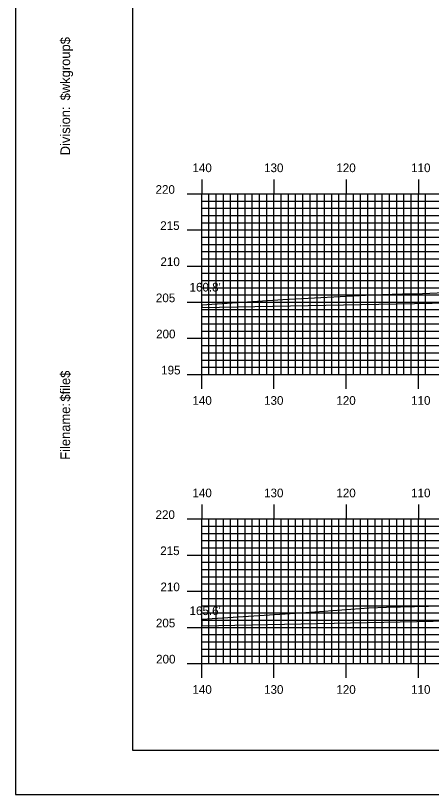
# Model space of a CAD drawing. Extents: x 1821605 to 1821948, y 442591 to 442811.
# Drawn here: x 1821605 to 1821662.5, y 442590.5 to 442698.3 of the extents above; entities that cross this region are included whole.
import ezdxf

# ---------------------------------------------------------------- set-up
doc = ezdxf.new("R2010")
doc.units = 0
for name, color, linetype in [('ANNOTATION', 7, 'Continuous'), ('BORDER', 7, 'Continuous'), ('D_Text_Standard', 7, 'Continuous'), ('H_V ANNOTATION', 7, 'Continuous'), ('MAJOR', 7, 'Continuous'), ('MINOR', 7, 'Continuous'), ('PLOT BOUNDARY', 7, 'Continuous'), ('S_Roadway_Centerline', 7, 'Continuous')]:
    doc.layers.add(name, color=color, linetype=linetype)

msp = doc.modelspace()

# ---------------------------------------------------------------- linework, layer by layer
at = {"layer": 'ANNOTATION'}
for p, q in [((1821726.4, 442659.78), (1821630.74, 442657.87)), ((1821630.74, 442658.31), (1821630.74, 442657.87)), ((1821726.4, 442615.77), (1821630.74, 442613.85)), ((1821630.74, 442614.78), (1821630.74, 442613.85))]:
    msp.add_line(p, q, dxfattribs=at)
at = {"layer": 'BORDER'}
msp.add_lwpolyline([(1821621.14, 442596.67), (1821941.14, 442596.67), (1821941.14, 442806.67), (1821621.14, 442806.67)], close=True, dxfattribs=at)
at = {"layer": 'MAJOR'}
for p, q in [((1821630.74, 442675.67), (1821630.74, 442673.67)), ((1821640.74, 442675.67), (1821640.74, 442673.67)), ((1821650.74, 442675.67), (1821650.74, 442673.67)), ((1821660.74, 442675.67), (1821660.74, 442673.67)), ((1821628.74, 442673.67), (1821630.74, 442673.67)), ((1821630.74, 442673.67), (1821910.74, 442673.67)), ((1821630.74, 442648.67), (1821630.74, 442673.67)), ((1821630.74, 442648.67), (1821630.74, 442673.67)), ((1821630.74, 442673.67), (1821910.74, 442673.67)), ((1821640.74, 442648.67), (1821640.74, 442673.67)), ((1821650.74, 442648.67), (1821650.74, 442673.67)), ((1821660.74, 442648.67), (1821660.74, 442673.67)), ((1821628.74, 442668.67), (1821630.74, 442668.67)), ((1821630.74, 442668.67), (1821910.74, 442668.67)), ((1821628.74, 442663.67), (1821630.74, 442663.67)), ((1821630.74, 442663.67), (1821910.74, 442663.67)), ((1821628.74, 442658.67), (1821630.74, 442658.67)), ((1821630.74, 442658.67), (1821910.74, 442658.67)), ((1821628.74, 442653.67), (1821630.74, 442653.67)), ((1821630.74, 442653.67), (1821910.74, 442653.67)), ((1821628.74, 442648.67), (1821630.74, 442648.67)), ((1821630.74, 442648.67), (1821910.74, 442648.67)), ((1821630.74, 442648.67), (1821910.74, 442648.67)), ((1821630.74, 442646.66), (1821630.74, 442648.67)), ((1821640.74, 442646.66), (1821640.74, 442648.67)), ((1821650.74, 442646.66), (1821650.74, 442648.67)), ((1821660.74, 442646.66), (1821660.74, 442648.67)), ((1821630.74, 442630.67), (1821630.74, 442628.67)), ((1821640.74, 442630.67), (1821640.74, 442628.67)), ((1821650.74, 442630.67), (1821650.74, 442628.67)), ((1821660.74, 442630.67), (1821660.74, 442628.67)), ((1821628.74, 442628.67), (1821630.74, 442628.67)), ((1821630.74, 442628.67), (1821910.74, 442628.67)), ((1821630.74, 442608.67), (1821630.74, 442628.67)), ((1821630.74, 442608.67), (1821630.74, 442628.67)), ((1821630.74, 442628.67), (1821910.74, 442628.67)), ((1821640.74, 442608.67), (1821640.74, 442628.67)), ((1821650.74, 442608.67), (1821650.74, 442628.67)), ((1821660.74, 442608.67), (1821660.74, 442628.67)), ((1821628.74, 442623.67), (1821630.74, 442623.67)), ((1821630.74, 442623.67), (1821910.74, 442623.67)), ((1821628.74, 442618.67), (1821630.74, 442618.67)), ((1821630.74, 442618.67), (1821910.74, 442618.67)), ((1821628.74, 442613.67), (1821630.74, 442613.67)), ((1821630.74, 442613.67), (1821910.74, 442613.67)), ((1821628.74, 442608.67), (1821630.74, 442608.67)), ((1821630.74, 442608.67), (1821910.74, 442608.67)), ((1821630.74, 442608.67), (1821910.74, 442608.67)), ((1821630.74, 442606.66), (1821630.74, 442608.67)), ((1821640.74, 442606.66), (1821640.74, 442608.67)), ((1821650.74, 442606.66), (1821650.74, 442608.67)), ((1821660.74, 442606.66), (1821660.74, 442608.67))]:
    msp.add_line(p, q, dxfattribs=at)
at = {"layer": 'MINOR'}
for p, q in [((1821631.74, 442648.67), (1821631.74, 442673.67)), ((1821632.74, 442648.67), (1821632.74, 442673.67)), ((1821633.74, 442648.67), (1821633.74, 442673.67)), ((1821634.74, 442648.67), (1821634.74, 442673.67)), ((1821635.74, 442648.67), (1821635.74, 442673.67)), ((1821636.74, 442648.67), (1821636.74, 442673.67)), ((1821637.74, 442648.67), (1821637.74, 442673.67)), ((1821638.74, 442648.67), (1821638.74, 442673.67)), ((1821639.74, 442648.67), (1821639.74, 442673.67)), ((1821641.74, 442648.67), (1821641.74, 442673.67)), ((1821642.74, 442648.67), (1821642.74, 442673.67)), ((1821643.74, 442648.67), (1821643.74, 442673.67)), ((1821644.74, 442648.67), (1821644.74, 442673.67)), ((1821645.74, 442648.67), (1821645.74, 442673.67)), ((1821646.74, 442648.67), (1821646.74, 442673.67)), ((1821647.74, 442648.67), (1821647.74, 442673.67)), ((1821648.74, 442648.67), (1821648.74, 442673.67)), ((1821649.74, 442648.67), (1821649.74, 442673.67)), ((1821651.74, 442648.67), (1821651.74, 442673.67)), ((1821652.74, 442648.67), (1821652.74, 442673.67)), ((1821653.74, 442648.67), (1821653.74, 442673.67)), ((1821654.74, 442648.67), (1821654.74, 442673.67)), ((1821655.74, 442648.67), (1821655.74, 442673.67)), ((1821656.74, 442648.67), (1821656.74, 442673.67)), ((1821657.74, 442648.67), (1821657.74, 442673.67)), ((1821658.74, 442648.67), (1821658.74, 442673.67)), ((1821659.74, 442648.67), (1821659.74, 442673.67)), ((1821661.74, 442648.67), (1821661.74, 442673.67)), ((1821630.74, 442672.67), (1821910.74, 442672.67)), ((1821630.74, 442672.67), (1821632.75, 442672.67)), ((1821630.74, 442671.67), (1821910.74, 442671.67)), ((1821630.74, 442671.67), (1821632.75, 442671.67)), ((1821630.74, 442670.67), (1821910.74, 442670.67)), ((1821630.74, 442670.67), (1821632.75, 442670.67)), ((1821630.74, 442669.67), (1821910.74, 442669.67)), ((1821630.74, 442669.67), (1821632.75, 442669.67)), ((1821630.74, 442667.67), (1821910.74, 442667.67)), ((1821630.74, 442667.67), (1821632.75, 442667.67)), ((1821630.74, 442666.67), (1821910.74, 442666.67)), ((1821630.74, 442666.67), (1821632.75, 442666.67)), ((1821630.74, 442665.67), (1821910.74, 442665.67)), ((1821630.74, 442665.67), (1821632.75, 442665.67)), ((1821630.74, 442664.67), (1821910.74, 442664.67)), ((1821630.74, 442664.67), (1821632.75, 442664.67)), ((1821630.74, 442662.67), (1821910.74, 442662.67)), ((1821630.74, 442662.67), (1821632.75, 442662.67)), ((1821630.74, 442661.67), (1821910.74, 442661.67)), ((1821630.74, 442661.67), (1821632.75, 442661.67)), ((1821630.74, 442660.67), (1821910.74, 442660.67)), ((1821630.74, 442660.67), (1821632.75, 442660.67)), ((1821630.74, 442659.67), (1821910.74, 442659.67)), ((1821630.74, 442659.67), (1821632.75, 442659.67)), ((1821630.74, 442657.67), (1821910.74, 442657.67)), ((1821630.74, 442657.67), (1821632.75, 442657.67)), ((1821630.74, 442656.67), (1821910.74, 442656.67)), ((1821630.74, 442656.67), (1821632.75, 442656.67)), ((1821630.74, 442655.67), (1821910.74, 442655.67)), ((1821630.74, 442655.67), (1821632.75, 442655.67)), ((1821630.74, 442654.67), (1821910.74, 442654.67)), ((1821630.74, 442654.67), (1821632.75, 442654.67)), ((1821630.74, 442652.67), (1821910.74, 442652.67)), ((1821630.74, 442652.67), (1821632.75, 442652.67)), ((1821630.74, 442651.67), (1821910.74, 442651.67)), ((1821630.74, 442651.67), (1821632.75, 442651.67)), ((1821630.74, 442650.67), (1821910.74, 442650.67)), ((1821630.74, 442650.67), (1821632.75, 442650.67)), ((1821630.74, 442649.67), (1821910.74, 442649.67)), ((1821630.74, 442649.67), (1821632.75, 442649.67)), ((1821631.74, 442608.67), (1821631.74, 442628.67)), ((1821632.74, 442608.67), (1821632.74, 442628.67)), ((1821633.74, 442608.67), (1821633.74, 442628.67)), ((1821634.74, 442608.67), (1821634.74, 442628.67)), ((1821635.74, 442608.67), (1821635.74, 442628.67)), ((1821636.74, 442608.67), (1821636.74, 442628.67)), ((1821637.74, 442608.67), (1821637.74, 442628.67)), ((1821638.74, 442608.67), (1821638.74, 442628.67)), ((1821639.74, 442608.67), (1821639.74, 442628.67)), ((1821641.74, 442608.67), (1821641.74, 442628.67)), ((1821642.74, 442608.67), (1821642.74, 442628.67)), ((1821643.74, 442608.67), (1821643.74, 442628.67)), ((1821644.74, 442608.67), (1821644.74, 442628.67)), ((1821645.74, 442608.67), (1821645.74, 442628.67)), ((1821646.74, 442608.67), (1821646.74, 442628.67)), ((1821647.74, 442608.67), (1821647.74, 442628.67)), ((1821648.74, 442608.67), (1821648.74, 442628.67)), ((1821649.74, 442608.67), (1821649.74, 442628.67)), ((1821651.74, 442608.67), (1821651.74, 442628.67)), ((1821652.74, 442608.67), (1821652.74, 442628.67)), ((1821653.74, 442608.67), (1821653.74, 442628.67)), ((1821654.74, 442608.67), (1821654.74, 442628.67)), ((1821655.74, 442608.67), (1821655.74, 442628.67)), ((1821656.74, 442608.67), (1821656.74, 442628.67)), ((1821657.74, 442608.67), (1821657.74, 442628.67)), ((1821658.74, 442608.67), (1821658.74, 442628.67)), ((1821659.74, 442608.67), (1821659.74, 442628.67)), ((1821661.74, 442608.67), (1821661.74, 442628.67)), ((1821630.74, 442627.67), (1821910.74, 442627.67)), ((1821630.74, 442627.67), (1821632.75, 442627.67)), ((1821630.74, 442626.67), (1821910.74, 442626.67)), ((1821630.74, 442626.67), (1821632.75, 442626.67)), ((1821630.74, 442625.67), (1821910.74, 442625.67)), ((1821630.74, 442625.67), (1821632.75, 442625.67)), ((1821630.74, 442624.67), (1821910.74, 442624.67)), ((1821630.74, 442624.67), (1821632.75, 442624.67)), ((1821630.74, 442622.67), (1821910.74, 442622.67)), ((1821630.74, 442622.67), (1821632.75, 442622.67)), ((1821630.74, 442621.67), (1821910.74, 442621.67)), ((1821630.74, 442621.67), (1821632.75, 442621.67)), ((1821630.74, 442620.67), (1821910.74, 442620.67)), ((1821630.74, 442620.67), (1821632.75, 442620.67)), ((1821630.74, 442619.67), (1821910.74, 442619.67)), ((1821630.74, 442619.67), (1821632.75, 442619.67)), ((1821630.74, 442617.67), (1821910.74, 442617.67)), ((1821630.74, 442617.67), (1821632.75, 442617.67)), ((1821630.74, 442616.67), (1821910.74, 442616.67)), ((1821630.74, 442616.67), (1821632.75, 442616.67)), ((1821630.74, 442615.67), (1821910.74, 442615.67)), ((1821630.74, 442615.67), (1821632.75, 442615.67)), ((1821630.74, 442614.67), (1821910.74, 442614.67)), ((1821630.74, 442614.67), (1821632.75, 442614.67)), ((1821630.74, 442612.67), (1821910.74, 442612.67)), ((1821630.74, 442612.67), (1821632.75, 442612.67)), ((1821630.74, 442611.67), (1821910.74, 442611.67)), ((1821630.74, 442611.67), (1821632.75, 442611.67)), ((1821630.74, 442610.67), (1821910.74, 442610.67)), ((1821630.74, 442610.67), (1821632.75, 442610.67)), ((1821630.74, 442609.67), (1821910.74, 442609.67)), ((1821630.74, 442609.67), (1821632.75, 442609.67))]:
    msp.add_line(p, q, dxfattribs=at)
at = {"layer": 'PLOT BOUNDARY'}
msp.add_lwpolyline([(1821604.96, 442590.55), (1821944.96, 442590.55), (1821944.96, 442810.55), (1821604.96, 442810.55)], close=True, dxfattribs=at)
at = {"layer": 'S_Roadway_Centerline'}
for points in [[(1821630.74, 442658.31), (1821641.95, 442659.06), (1821654.31, 442659.67), (1821658.52, 442659.83), (1821661.29, 442659.89), (1821670.37, 442660.31), (1821674.52, 442660.46), (1821677.77, 442660.52), (1821692.04, 442660.84), (1821699.95, 442660.98), (1821709.59, 442660.99), (1821714.85, 442661.05), (1821726.06, 442661.38)], [(1821630.74, 442614.78), (1821645.15, 442615.72), (1821653.89, 442616.35), (1821656.34, 442616.45), (1821666.02, 442616.68), (1821713.55, 442617.48), (1821722.12, 442617.92)]]:
    msp.add_lwpolyline(points, dxfattribs=at)

# ---------------------------------------------------------------- texts
at = {"layer": 'BORDER'}
for s, p in [('$wkgroup$', (1821612.51, 442686.6)), ('Division:', (1821612.51, 442679)), ('$file$', (1821612.51, 442644.92)), ('Filename:', (1821612.51, 442636.86))]:
    msp.add_text(s, height=1.339, rotation=90, dxfattribs=at).set_placement(p)
at = {"layer": 'D_Text_Standard'}
for s, p in [("160.8'", (1821629.05, 442660.15)), ("165.6'", (1821629.05, 442615.37))]:
    msp.add_text(s, height=1.2, dxfattribs=at).set_placement(p)
at = {"layer": 'H_V ANNOTATION'}
for s, p in [('140', (1821629.45, 442676.67)), ('130', (1821639.37, 442676.67)), ('120', (1821649.38, 442676.67)), ('110', (1821659.73, 442676.67)), ('220', (1821624.34, 442673.67)), ('215', (1821624.99, 442668.67)), ('210', (1821625.02, 442663.67)), ('205', (1821624.39, 442658.67)), ('200', (1821624.42, 442653.67)), ('195', (1821625.12, 442648.67)), ('140', (1821629.45, 442644.47)), ('130', (1821639.37, 442644.47)), ('120', (1821649.38, 442644.47)), ('110', (1821659.73, 442644.47)), ('140', (1821629.45, 442631.67)), ('130', (1821639.37, 442631.67)), ('120', (1821649.38, 442631.67)), ('110', (1821659.73, 442631.67)), ('220', (1821624.34, 442628.67)), ('215', (1821624.99, 442623.67)), ('210', (1821625.02, 442618.67)), ('205', (1821624.39, 442613.67)), ('200', (1821624.42, 442608.67)), ('140', (1821629.45, 442604.47)), ('130', (1821639.37, 442604.47)), ('120', (1821649.38, 442604.47)), ('110', (1821659.73, 442604.47))]:
    msp.add_text(s, height=1.2, dxfattribs=at).set_placement(p)
at = {"layer": 'MAJOR'}
for p in [(1821630.73, 442648.67), (1821630.73, 442608.67)]:
    msp.add_text('-', height=0.012, dxfattribs=at).set_placement(p)

doc.saveas('drawing.dxf')
